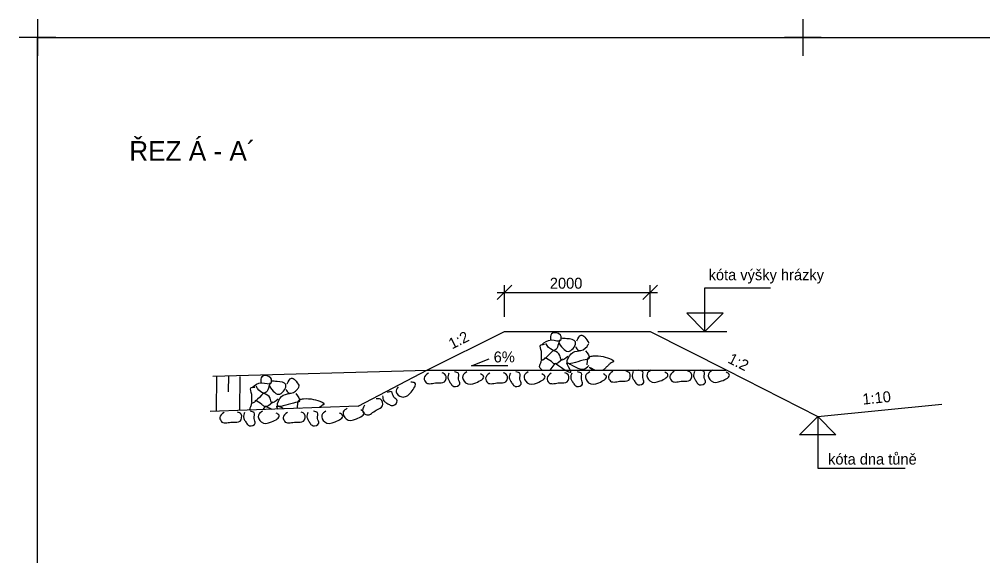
# Model space of a CAD drawing. Extents: x -463095.2 to -463015.6, y -1105044.4 to -1104976.7.
# Drawn here: x -463058.63 to -463032.2, y -1104991.46 to -1104976.73 of the extents above; entities that cross this region are included whole.
import ezdxf

# ---------------------------------------------------------------- set-up
doc = ezdxf.new("R2010")
doc.units = 0
for name, color, linetype in [('Implicitní', 7, 'Continuous'), ('KOTA', 7, 'Continuous'), ('KOTA_DELKY', 7, 'Continuous'), ('NS_V_PF', 7, 'Continuous'), ('REZY_PF_PUVODNI', 7, 'Continuous'), ('SKLON', 7, 'Continuous'), ('Vrstva 14', 7, 'Continuous')]:
    doc.layers.add(name, color=color, linetype=linetype)

msp = doc.modelspace()

# ---------------------------------------------------------------- linework, layer by layer
at = {"layer": 'Implicitní'}
for p, q in [((-463058.132, -1104976.732), (-463058.132, -1104977.732)), ((-463058.132, -1104976.732), (-463058.132, -1104977.732)), ((-463058.132, -1104976.732), (-463058.132, -1104977.732)), ((-463058.132, -1104976.732), (-463058.132, -1104977.732)), ((-463058.132, -1104976.732), (-463058.132, -1104977.732)), ((-463058.132, -1104976.732), (-463058.132, -1104977.732)), ((-463058.132, -1104976.732), (-463058.132, -1104977.732)), ((-463058.132, -1104976.732), (-463058.132, -1104977.732)), ((-463058.132, -1104976.732), (-463058.132, -1104977.732)), ((-463058.132, -1104976.732), (-463058.132, -1104977.732)), ((-463058.132, -1104976.732), (-463058.132, -1104977.732)), ((-463058.132, -1104976.732), (-463058.132, -1104977.732)), ((-463058.132, -1104976.732), (-463058.132, -1104977.732)), ((-463058.132, -1104976.732), (-463058.132, -1104977.732)), ((-463058.132, -1104976.732), (-463058.132, -1104977.732)), ((-463058.132, -1104976.732), (-463058.132, -1104977.732)), ((-463037.132, -1104976.732), (-463037.132, -1104977.732)), ((-463037.132, -1104976.732), (-463037.132, -1104977.732)), ((-463037.132, -1104976.732), (-463037.132, -1104977.732)), ((-463037.132, -1104976.732), (-463037.132, -1104977.732)), ((-463037.132, -1104976.732), (-463037.132, -1104977.732)), ((-463037.132, -1104976.732), (-463037.132, -1104977.732)), ((-463037.132, -1104976.732), (-463037.132, -1104977.732)), ((-463037.132, -1104976.732), (-463037.132, -1104977.732)), ((-463037.132, -1104976.732), (-463037.132, -1104977.732)), ((-463037.132, -1104976.732), (-463037.132, -1104977.732)), ((-463037.132, -1104976.732), (-463037.132, -1104977.732)), ((-463037.132, -1104976.732), (-463037.132, -1104977.732)), ((-463037.132, -1104976.732), (-463037.132, -1104977.732)), ((-463037.132, -1104976.732), (-463037.132, -1104977.732)), ((-463037.132, -1104976.732), (-463037.132, -1104977.732)), ((-463037.132, -1104976.732), (-463037.132, -1104977.732)), ((-463037.132, -1104976.732), (-463037.132, -1104977.732)), ((-463037.132, -1104976.732), (-463037.132, -1104977.732)), ((-463037.132, -1104976.732), (-463037.132, -1104977.732)), ((-463037.132, -1104976.732), (-463037.132, -1104977.732)), ((-463037.132, -1104976.732), (-463037.132, -1104977.732)), ((-463037.132, -1104976.732), (-463037.132, -1104977.732)), ((-463037.132, -1104976.732), (-463037.132, -1104977.732)), ((-463037.132, -1104976.732), (-463037.132, -1104977.732)), ((-463057.632, -1104977.232), (-463058.632, -1104977.232)), ((-463057.632, -1104977.232), (-463058.632, -1104977.232)), ((-463057.632, -1104977.232), (-463058.632, -1104977.232)), ((-463057.632, -1104977.232), (-463058.632, -1104977.232)), ((-463057.632, -1104977.232), (-463058.632, -1104977.232)), ((-463036.632, -1104977.232), (-463037.632, -1104977.232)), ((-463036.632, -1104977.232), (-463037.632, -1104977.232)), ((-463036.632, -1104977.232), (-463037.632, -1104977.232)), ((-463036.632, -1104977.232), (-463037.632, -1104977.232)), ((-463036.632, -1104977.232), (-463037.632, -1104977.232)), ((-463036.632, -1104977.232), (-463037.632, -1104977.232)), ((-463036.632, -1104977.232), (-463037.632, -1104977.232)), ((-463036.632, -1104977.232), (-463037.632, -1104977.232))]:
    msp.add_line(p, q, dxfattribs=at)
msp.add_lwpolyline([(-463058.132, -1104977.232), (-463016.132, -1104977.232), (-463016.132, -1105036.632), (-463058.132, -1105036.632)], close=True, dxfattribs=at)
at = {"layer": 'KOTA'}
for points in [[(-463039.817, -1104984.8), (-463040.317, -1104984.8), (-463039.817, -1104985.3), (-463039.817, -1104984.1), (-463038.017, -1104984.1)], [(-463039.817, -1104985.3), (-463039.317, -1104984.8), (-463039.817, -1104984.8)], [(-463043.319, -1104985.3), (-463041.319, -1104985.3)], [(-463041.112, -1104985.3), (-463039.817, -1104985.3), (-463039.217, -1104985.3)], [(-463036.723, -1104988.135), (-463037.223, -1104988.135), (-463036.723, -1104987.635), (-463036.723, -1104989.054), (-463034.322, -1104989.054)], [(-463036.723, -1104987.635), (-463036.223, -1104988.135), (-463036.723, -1104988.135)]]:
    msp.add_lwpolyline(points, dxfattribs=at)
at = {"layer": 'KOTA_DELKY'}
for points in [[(-463045.519, -1104984.427), (-463045.119, -1104984.027)], [(-463045.319, -1104984.9), (-463045.319, -1104984.027)], [(-463041.519, -1104984.427), (-463041.119, -1104984.027)], [(-463041.319, -1104984.9), (-463041.319, -1104984.027)], [(-463045.519, -1104984.227), (-463041.119, -1104984.227)]]:
    msp.add_lwpolyline(points, dxfattribs=at)
at = {"layer": 'NS_V_PF'}
for points in [[(-463047.452, -1104986.367), (-463045.319, -1104985.3), (-463043.319, -1104985.3), (-463041.319, -1104985.3), (-463039.238, -1104986.358)], [(-463039.238, -1104986.358), (-463036.723, -1104987.635), (-463033.319, -1104987.294)]]:
    msp.add_lwpolyline(points, dxfattribs=at)
at = {"layer": 'REZY_PF_PUVODNI'}
msp.add_lwpolyline([(-463053.319, -1104986.525), (-463047.443, -1104986.366)], dxfattribs=at)
at = {"layer": 'Vrstva 14'}
for p, q in [((-463043.939, -1104986.181), (-463044.073, -1104986.366)), ((-463052.886, -1104986.959), (-463052.88, -1104986.507)), ((-463047.443, -1104986.366), (-463049.34, -1104987.358)), ((-463047.443, -1104986.366), (-463039.242, -1104986.366)), ((-463042.993, -1104986.279), (-463042.906, -1104986.366)), ((-463042.835, -1104986.366), (-463042.955, -1104986.299)), ((-463053.224, -1104987.489), (-463053.21, -1104986.515)), ((-463052.581, -1104987.467), (-463052.568, -1104986.533)), ((-463049.334, -1104987.354), (-463053.398, -1104987.495)), ((-463051.887, -1104987.356), (-463051.951, -1104987.445)), ((-463051.873, -1104987.35), (-463051.7, -1104987.436)), ((-463050.957, -1104987.411), (-463050.953, -1104987.408))]:
    msp.add_line(p, q, dxfattribs=at)
msp.add_lwpolyline([(-463045.224, -1104986.24), (-463046.227, -1104986.24), (-463045.741, -1104986.052)], dxfattribs=at)
for points in [[(-463044.291, -1104985.665), (-463044.031, -1104985.535), (-463043.771, -1104985.535), (-463043.783, -1104985.405), (-463044.031, -1104985.369), (-463044.055, -1104985.523)], [(-463043.335, -1104985.559), (-463043.217, -1104985.405), (-463043.005, -1104985.617)], [(-463043.985, -1104985.819), (-463044.303, -1104986.079), (-463044.303, -1104985.855), (-463044.327, -1104985.677), (-463044.221, -1104985.653)], [(-463043.807, -1104985.535), (-463043.961, -1104985.819), (-463044.149, -1104985.689), (-463044.185, -1104985.629)], [(-463043.819, -1104985.629), (-463043.535, -1104985.843), (-463043.371, -1104985.583), (-463043.607, -1104985.499), (-463043.761, -1104985.487)], [(-463043.371, -1104985.713), (-463043.277, -1104985.819), (-463043.053, -1104985.713), (-463043.005, -1104985.629)], [(-463043.583, -1104985.985), (-463043.761, -1104986.079), (-463043.795, -1104985.961), (-463043.961, -1104985.831)], [(-463043.099, -1104985.831), (-463042.993, -1104986.033), (-463043.159, -1104986.091), (-463043.595, -1104986.151), (-463043.489, -1104985.913), (-463043.265, -1104985.831)], [(-463043.053, -1104986.221), (-463043.049, -1104986.182), (-463043.044, -1104986.143), (-463043.039, -1104986.104), (-463043.033, -1104986.065), (-463043.031, -1104986.055), (-463043.028, -1104986.045), (-463043.019, -1104986.028), (-463042.988, -1104986), (-463042.887, -1104985.971), (-463042.61, -1104985.992), (-463042.373, -1104986.068), (-463042.325, -1104986.109), (-463042.327, -1104986.127), (-463042.337, -1104986.136), (-463042.343, -1104986.139), (-463042.347, -1104986.141), (-463042.349, -1104986.142), (-463042.351, -1104986.143), (-463042.368, -1104986.15), (-463042.417, -1104986.183), (-463042.483, -1104986.242), (-463042.55, -1104986.308), (-463042.584, -1104986.339), (-463042.618, -1104986.366)], [(-463044.288, -1104986.366), (-463044.291, -1104986.363), (-463044.305, -1104986.349), (-463044.34, -1104986.306), (-463044.353, -1104986.276), (-463044.354, -1104986.26), (-463044.353, -1104986.253), (-463044.351, -1104986.245), (-463044.337, -1104986.202), (-463044.323, -1104986.16), (-463044.308, -1104986.117), (-463044.293, -1104986.075)], [(-463043.729, -1104986.063), (-463043.949, -1104986.187), (-463044.031, -1104986.127), (-463044.209, -1104986.021)], [(-463043.925, -1104986.175), (-463043.501, -1104986.387), (-463043.607, -1104986.175), (-463043.159, -1104986.339), (-463043.005, -1104986.233)], [(-463052.239, -1104986.84), (-463051.979, -1104986.71), (-463051.719, -1104986.71), (-463051.731, -1104986.58), (-463051.979, -1104986.544), (-463052.003, -1104986.698)], [(-463047.404, -1104986.443), (-463047.521, -1104986.586), (-463047.463, -1104986.708), (-463047.172, -1104986.708), (-463046.966, -1104986.682), (-463046.935, -1104986.496), (-463047.032, -1104986.435)], [(-463046.841, -1104986.443), (-463046.87, -1104986.578), (-463046.839, -1104986.652), (-463046.784, -1104986.741), (-463046.707, -1104986.808), (-463046.547, -1104986.744), (-463046.579, -1104986.611), (-463046.579, -1104986.45), (-463046.688, -1104986.413)], [(-463046.35, -1104986.413), (-463046.462, -1104986.515), (-463046.383, -1104986.707), (-463046.1, -1104986.707), (-463045.891, -1104986.531), (-463045.975, -1104986.462)], [(-463045.719, -1104986.443), (-463045.836, -1104986.586), (-463045.777, -1104986.708), (-463045.487, -1104986.708), (-463045.28, -1104986.682), (-463045.25, -1104986.496), (-463045.347, -1104986.435)], [(-463045.156, -1104986.443), (-463045.185, -1104986.578), (-463045.154, -1104986.652), (-463045.099, -1104986.741), (-463045.022, -1104986.808), (-463044.861, -1104986.744), (-463044.893, -1104986.611), (-463044.893, -1104986.45), (-463045.003, -1104986.413)], [(-463044.664, -1104986.413), (-463044.776, -1104986.515), (-463044.697, -1104986.707), (-463044.415, -1104986.707), (-463044.206, -1104986.531), (-463044.29, -1104986.462)], [(-463044.033, -1104986.443), (-463044.15, -1104986.586), (-463044.092, -1104986.708), (-463043.801, -1104986.708), (-463043.595, -1104986.682), (-463043.564, -1104986.496), (-463043.661, -1104986.435)], [(-463043.47, -1104986.443), (-463043.499, -1104986.578), (-463043.469, -1104986.652), (-463043.413, -1104986.741), (-463043.336, -1104986.808), (-463043.176, -1104986.744), (-463043.208, -1104986.611), (-463043.208, -1104986.45), (-463043.317, -1104986.413)], [(-463042.979, -1104986.413), (-463043.091, -1104986.515), (-463043.012, -1104986.707), (-463042.729, -1104986.707), (-463042.52, -1104986.531), (-463042.604, -1104986.462)], [(-463042.348, -1104986.396), (-463042.466, -1104986.539), (-463042.407, -1104986.662), (-463042.117, -1104986.662), (-463041.91, -1104986.636), (-463041.88, -1104986.45), (-463041.976, -1104986.389)], [(-463041.786, -1104986.396), (-463041.814, -1104986.532), (-463041.784, -1104986.606), (-463041.728, -1104986.695), (-463041.651, -1104986.762), (-463041.491, -1104986.698), (-463041.523, -1104986.565), (-463041.523, -1104986.403), (-463041.632, -1104986.367)], [(-463041.294, -1104986.367), (-463041.406, -1104986.469), (-463041.327, -1104986.66), (-463041.044, -1104986.66), (-463040.835, -1104986.484), (-463040.92, -1104986.415)], [(-463040.663, -1104986.396), (-463040.78, -1104986.539), (-463040.722, -1104986.662), (-463040.431, -1104986.662), (-463040.225, -1104986.636), (-463040.194, -1104986.45), (-463040.291, -1104986.389)], [(-463040.1, -1104986.396), (-463040.129, -1104986.532), (-463040.098, -1104986.606), (-463040.043, -1104986.695), (-463039.966, -1104986.762), (-463039.806, -1104986.698), (-463039.838, -1104986.565), (-463039.838, -1104986.403), (-463039.947, -1104986.367)], [(-463039.609, -1104986.367), (-463039.721, -1104986.469), (-463039.642, -1104986.66), (-463039.359, -1104986.66), (-463039.15, -1104986.484), (-463039.234, -1104986.415)], [(-463051.755, -1104986.71), (-463051.909, -1104986.994), (-463052.097, -1104986.864), (-463052.133, -1104986.804)], [(-463051.767, -1104986.804), (-463051.483, -1104987.018), (-463051.319, -1104986.758), (-463051.555, -1104986.674), (-463051.709, -1104986.662)], [(-463051.283, -1104986.734), (-463051.165, -1104986.58), (-463050.953, -1104986.792)], [(-463048.238, -1104986.82), (-463048.291, -1104986.962), (-463048.134, -1104987.096), (-463047.882, -1104986.967), (-463047.777, -1104986.715), (-463047.883, -1104986.692)], [(-463051.933, -1104986.994), (-463052.251, -1104987.254), (-463052.251, -1104987.03), (-463052.275, -1104986.852), (-463052.169, -1104986.828)], [(-463051.531, -1104987.16), (-463051.709, -1104987.254), (-463051.743, -1104987.136), (-463051.909, -1104987.006)], [(-463051.047, -1104987.006), (-463050.941, -1104987.208), (-463051.107, -1104987.266), (-463051.543, -1104987.326), (-463051.437, -1104987.088), (-463051.213, -1104987.006)], [(-463051.319, -1104986.888), (-463051.225, -1104986.994), (-463051.001, -1104986.888), (-463050.953, -1104986.804)], [(-463048.662, -1104987.07), (-463048.626, -1104987.204), (-463048.565, -1104987.256), (-463048.475, -1104987.31), (-463048.376, -1104987.334), (-463048.262, -1104987.204), (-463048.352, -1104987.101), (-463048.425, -1104986.957), (-463048.539, -1104986.974)], [(-463052.298, -1104987.457), (-463052.302, -1104987.439), (-463052.299, -1104987.42), (-463052.285, -1104987.377), (-463052.27, -1104987.335), (-463052.255, -1104987.293), (-463052.241, -1104987.25)], [(-463051.677, -1104987.238), (-463051.897, -1104987.362), (-463051.979, -1104987.302), (-463052.157, -1104987.196)], [(-463051.001, -1104987.396), (-463050.996, -1104987.357), (-463050.991, -1104987.318), (-463050.986, -1104987.279), (-463050.981, -1104987.24), (-463050.979, -1104987.23), (-463050.976, -1104987.22), (-463050.966, -1104987.203), (-463050.935, -1104987.175), (-463050.835, -1104987.146), (-463050.557, -1104987.167), (-463050.321, -1104987.243), (-463050.272, -1104987.284), (-463050.275, -1104987.302), (-463050.284, -1104987.311), (-463050.291, -1104987.314), (-463050.294, -1104987.316), (-463050.299, -1104987.318), (-463050.305, -1104987.321), (-463050.312, -1104987.324), (-463050.325, -1104987.331), (-463050.351, -1104987.348), (-463050.377, -1104987.368), (-463050.404, -1104987.391)], [(-463049.163, -1104987.327), (-463049.202, -1104987.508), (-463049.094, -1104987.59), (-463048.835, -1104987.457), (-463048.663, -1104987.34), (-463048.721, -1104987.161), (-463048.835, -1104987.151)], [(-463053.012, -1104987.521), (-463053.13, -1104987.664), (-463053.071, -1104987.786), (-463052.781, -1104987.786), (-463052.574, -1104987.761), (-463052.544, -1104987.575), (-463052.64, -1104987.514)], [(-463052.45, -1104987.521), (-463052.478, -1104987.656), (-463052.448, -1104987.731), (-463052.393, -1104987.82), (-463052.315, -1104987.887), (-463052.155, -1104987.822), (-463052.187, -1104987.69), (-463052.187, -1104987.528), (-463052.296, -1104987.492)], [(-463051.958, -1104987.492), (-463052.07, -1104987.594), (-463051.991, -1104987.785), (-463051.708, -1104987.785), (-463051.5, -1104987.609), (-463051.584, -1104987.54)], [(-463051.532, -1104987.431), (-463051.542, -1104987.416), (-463051.551, -1104987.401), (-463051.555, -1104987.395), (-463051.558, -1104987.389), (-463051.561, -1104987.383), (-463051.563, -1104987.377), (-463051.565, -1104987.372), (-463051.566, -1104987.368), (-463051.566, -1104987.363), (-463051.566, -1104987.359), (-463051.562, -1104987.353), (-463051.555, -1104987.35), (-463051.529, -1104987.349), (-463051.503, -1104987.354), (-463051.489, -1104987.358), (-463051.474, -1104987.364), (-463051.454, -1104987.374), (-463051.448, -1104987.378), (-463051.412, -1104987.401), (-463051.377, -1104987.425)], [(-463051.272, -1104987.521), (-463051.39, -1104987.664), (-463051.331, -1104987.786), (-463051.041, -1104987.786), (-463050.834, -1104987.761), (-463050.804, -1104987.575), (-463050.9, -1104987.514)], [(-463050.71, -1104987.521), (-463050.738, -1104987.656), (-463050.708, -1104987.731), (-463050.652, -1104987.82), (-463050.575, -1104987.887), (-463050.415, -1104987.822), (-463050.447, -1104987.69), (-463050.447, -1104987.528), (-463050.556, -1104987.492)], [(-463050.218, -1104987.492), (-463050.33, -1104987.594), (-463050.251, -1104987.785), (-463049.968, -1104987.785), (-463049.76, -1104987.609), (-463049.844, -1104987.54)], [(-463049.63, -1104987.407), (-463049.742, -1104987.509), (-463049.663, -1104987.7), (-463049.38, -1104987.7), (-463049.171, -1104987.524), (-463049.255, -1104987.456)]]:
    msp.add_spline(points, degree=3, dxfattribs=at)

# ---------------------------------------------------------------- texts
at = {"layer": 'KOTA'}
for s, p in [('kóta výšky hrázky', (-463039.716, -1104983.895)), ('kóta dna tůně', (-463036.438, -1104988.954))]:
    msp.add_text(s, height=0.3, dxfattribs=at).set_placement(p)
at = {"layer": 'KOTA_DELKY'}
for s, p in [('2000', (-463044.073, -1104984.127)), ('6%', (-463045.614, -1104986.15))]:
    msp.add_text(s, height=0.3, dxfattribs=at).set_placement(p)
at = {"layer": 'SKLON'}
for s, rotation, p in [('1:2', 26.5651, (-463046.757, -1104985.796)), ('1:2', 333.0741, (-463039.212, -1104986.146)), ('1:10', 5.7106, (-463035.48, -1104987.31))]:
    msp.add_text(s, height=0.3, rotation=rotation, dxfattribs=at).set_placement(p)
at = {"layer": 'Vrstva 14'}
msp.add_text('ŘEZ Á - A´', height=0.536, dxfattribs=at).set_placement((-463055.613, -1104980.613))

doc.saveas('drawing.dxf')
